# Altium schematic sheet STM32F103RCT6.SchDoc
size A3
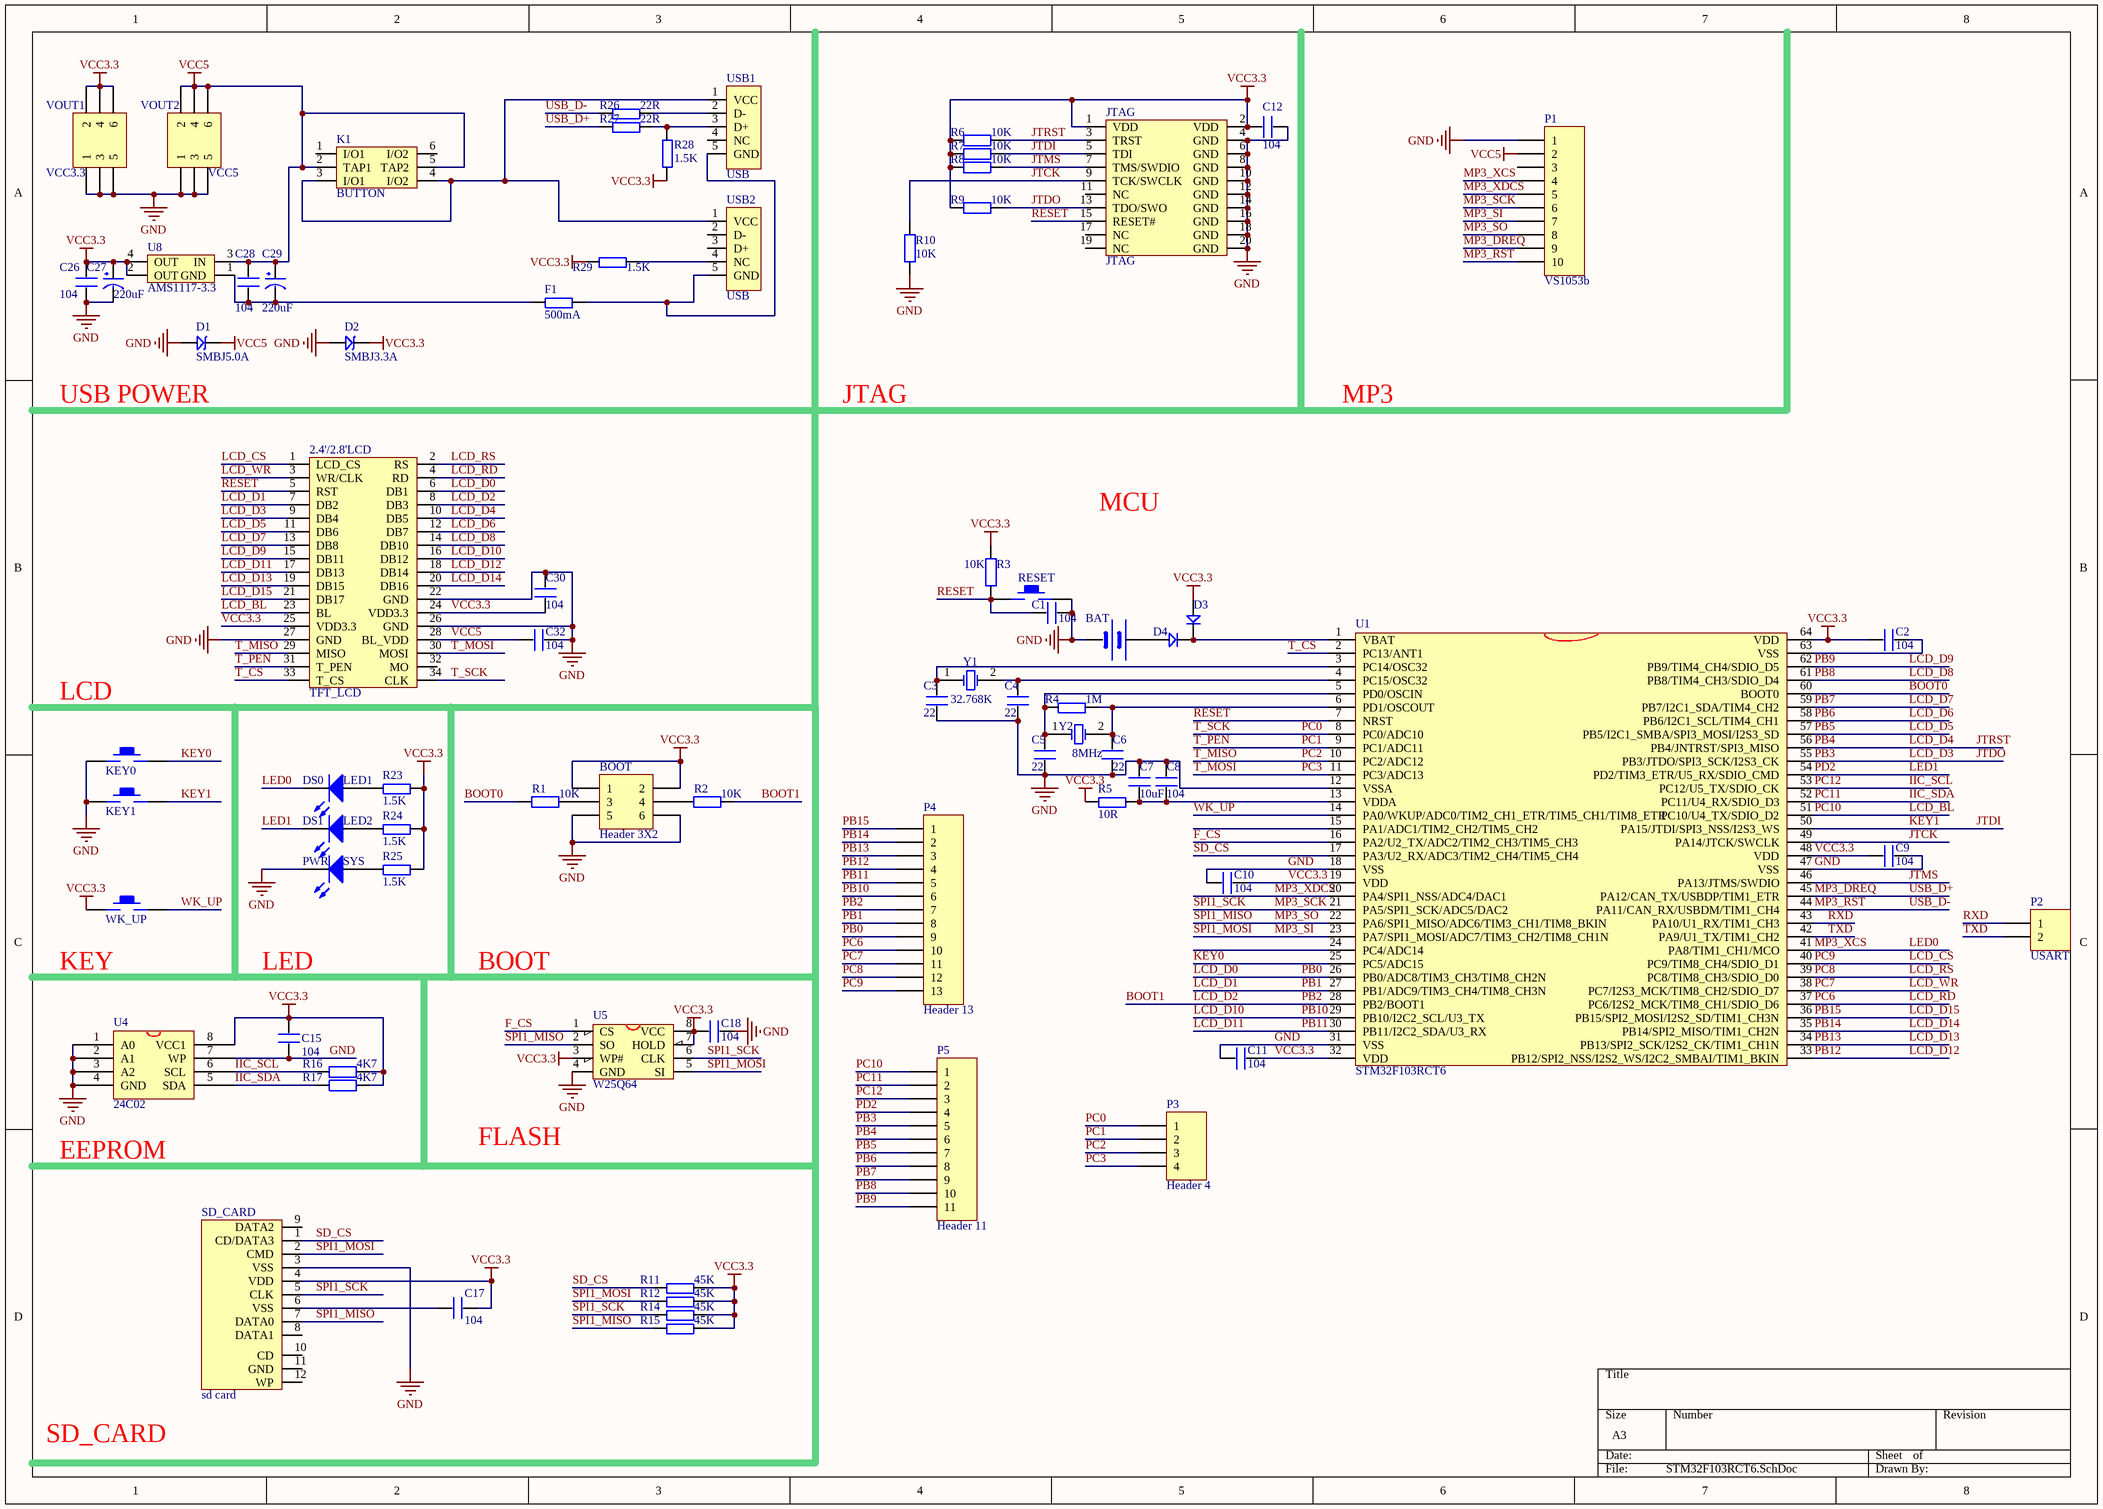
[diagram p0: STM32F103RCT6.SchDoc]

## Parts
2.4'/2.8'LCD  TFT_LCD  [HEAD2*17]
BAT  BATT  [BATM]  (value not drawn)
BOOT  Header 3X2  [HDR2X3]
C1  104  [0603P]
C2  104  [0603P]
C3  22  [0603P]
C4  22  [0603P]
C5  22  [0603P]
C6  22  [0603P]
C7  10uF  [0603P]
C8  104  [0603P]
C9  104  [0603P]
C10  104  [0603P]
C11  104  [0603P]
C12  104  [0603P]
C15  104  [0603P]
C17  104  [0603P]
C18  104  [0603P]
C26  104  [0603P]
C27  220uF  [CC6.56.5]
C28  104  [0603P]
C29  220uF  [CC6.56.5]
C30  104  [0603P]
C32  104  [0603P]
D1  SMBJ5.0A  [SMBJ]
D2  SMBJ3.3A  [SMBJ]
D3  1N4148  [DIODE_SOP]  (value not drawn)
D4  (no value)  [DIODE_SOP]
DS0  LED1  [SMDLED]
DS1  LED2  [SMDLED]
F1  500mA  [0805]
JTAG  JTAG  [JTAG_20]
K1  BUTTON  [BTN8.5*8.5]
KEY0  KEY_M  [KEY_M]  (value not drawn)
KEY1  KEY_M  [KEY_M]  (value not drawn)
P1  VS1053b  [HDR1X10]
P2  USART  [HDR1X2]
P3  Header 4  [HDR1X4]
P4  Header 13  [HDR1X13]
P5  Header 11  [HDR1X11]
PWR  SYS  [SMDLED]
R1  value 10K  [0603P]  (hidden comment: Res2)
R2  value 10K  [0603P]  (hidden comment: Res2)
R3  value 10K  [0603P]  (hidden comment: Res2)
R4  1M  [0603P]
R5  10R  [0603P]
R6  value 10K  [0603P]
R7  value 10K  [0603P]
R8  value 10K  [0603P]
R9  value 10K  [0603P]
R10  value 10K  [0603P]
R11  45K  [0603P]
R12  45K  [0603P]
R14  45K  [0603P]
R15  45K  [0603P]
R16  value 4K7  [0603P]
R17  value 4K7  [0603P]
R23  1.5K  [0603P]
R24  1.5K  [0603P]
R25  1.5K  [0603P]
R26  22R  [0603P]
R27  22R  [0603P]
R28  1.5K  [0603P]
R29  1.5K  [0603P]
RESET  KEY_M  [KEY_M]  (value not drawn)
SD_CARD  sd card  [SDCARD_L]
U1  STM32F103RCT6  [LQFP64]
U4  24C02  [SOP-8]
U5  W25Q64  [SOIC-8]
U8  AMS1117-3.3  [AMS1117]
USB1  USB  [USB/SM0.8-6H5]
USB2  USB  [USB/SM0.8-6H5]
VOUT1  VCC3.3  [HDR2X3]
VOUT2  VCC5  [HDR2X3]
WK_UP  KEY_M  [KEY_M]  (value not drawn)
Y1  32.768K  [XTAL32]
Y2  8MHz  [XTAL_US]

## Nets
GND: 2.4'/2.8'LCD.22(GND) 2.4'/2.8'LCD.26(GND) 2.4'/2.8'LCD.27(GND) BAT.2(GND) BOOT.5 BOOT.6 C1.2 C3.1 C4.1 C5.1 C6.1 C7.2 C8.2 C9.2 C10.1 C11.1 C12.2 C15.1 C18.2 C26.1 C27.2(GND) C30.2 C32.1 D1.1 D2.1 JTAG.4(GND) JTAG.6(GND) JTAG.8(GND) JTAG.10(GND) JTAG.12(GND) JTAG.14(GND) JTAG.16(GND) JTAG.18(GND) JTAG.20(GND) KEY0.1 KEY1.1 P1.1 PWR.2(K) R10.2 RESET.2 SD_CARD.3(VSS) U1.12(VSSA) U1.18(VSS) U1.31(VSS) U1.47(VSS) U4.1(A0) U4.2(A1) U4.3(A2) U4.4(GND) U4.7(WP) U5.4(GND) VOUT1.1 VOUT1.3 VOUT1.5 VOUT2.1 VOUT2.3 VOUT2.5
VCC3.3: 2.4'/2.8'LCD.24(VDD3.3) 2.4'/2.8'LCD.25(VDD3.3) BOOT.1 BOOT.2 C2.1 C9.1 C10.2 C11.2 C12.1 C15.2 C17.2 C18.1 C26.2 C27.1(VCC) C30.1 D2.2 D3.1 JTAG.1(VDD) JTAG.2(VDD) R3.2 R5.1 R6.1 R7.1 R8.1 R9.1 R11.2 R12.2 R14.2 R15.2 R16.2 R17.2 R23.2 R24.2 R25.2 R28.1 R29.1 SD_CARD.4(VDD) U1.19(VDD) U1.32(VDD) U1.48(VDD) U1.64(VDD) U4.8(VCC1) U5.3(WP#) U5.7(HOLD) U5.8(VCC) U8.2(OUT) U8.4(OUT) VOUT1.2 VOUT1.4 VOUT1.6 WK_UP.1
VCC5: 2.4'/2.8'LCD.28(BL_VDD) C28.2 C29.1(VCC) C32.2 D1.2 K1.2(TAP1) K1.5(TAP2) P1.2 U8.3(IN) VOUT2.2 VOUT2.4 VOUT2.6
BOOT0: R1.1 U1.60(BOOT0)
BOOT1: 2.4'/2.8'LCD.8(DB3) P4.7 R2.2 U1.28(PB2/BOOT1)  [also labelled LCD_D2, PB2]
F_CS: U1.16(PA2/U2_TX/ADC2/TIM2_CH3/TIM5_CH3) U5.1(CS)
IIC_SCL: P5.3 R16.1 U1.53(PC12/U5_TX/SDIO_CK) U4.6(SCL)  [also labelled PC12]
IIC_SDA: P5.2 R17.1 U1.52(PC11/U4_RX/SDIO_D3) U4.5(SDA)  [also labelled PC11]
JTCK: JTAG.9(TCK/SWCLK) R10.1 U1.49(PA14/JTCK/SWCLK)
JTDI: JTAG.5(TDI) KEY1.2 R7.2 U1.50(PA15/JTDI/SPI3_NSS/I2S3_WS)  [also labelled KEY1]
JTDO: 2.4'/2.8'LCD.9(DB4) JTAG.13(TDO/SWO) P5.5 R9.2 U1.55(PB3/JTDO/SPI3_SCK/I2S3_CK)  [also labelled LCD_D3, PB3]
JTMS: JTAG.7(TMS/SWDIO) R8.2 U1.46(PA13/JTMS/SWDIO)
JTRST: 2.4'/2.8'LCD.10(DB5) JTAG.3(TRST) P5.6 R6.2 U1.56(PB4/JNTRST/SPI3_MISO)  [also labelled LCD_D4, PB4]
KEY0: KEY0.2 U1.25(PC5/ADC15)
LCD_BL: 2.4'/2.8'LCD.23(BL) P5.1 U1.51(PC10/U4_TX/SDIO_D2)  [also labelled PC10]
LCD_CS: 2.4'/2.8'LCD.1(LCD_CS) P4.13 U1.40(PC9/TIM8_CH4/SDIO_D1)  [also labelled PC9]
LCD_D0: 2.4'/2.8'LCD.6(DB1) P4.9 U1.26(PB0/ADC8/TIM3_CH3/TIM8_CH2N)  [also labelled PB0]
LCD_D1: 2.4'/2.8'LCD.7(DB2) P4.8 U1.27(PB1/ADC9/TIM3_CH4/TIM8_CH3N)  [also labelled PB1]
LCD_D5: 2.4'/2.8'LCD.11(DB6) P5.7 U1.57(PB5/I2C1_SMBA/SPI3_MOSI/I2S3_SD)  [also labelled PB5]
LCD_D6: 2.4'/2.8'LCD.12(DB7) P5.8 U1.58(PB6/I2C1_SCL/TIM4_CH1)  [also labelled PB6]
LCD_D7: 2.4'/2.8'LCD.13(DB8) P5.9 U1.59(PB7/I2C1_SDA/TIM4_CH2)  [also labelled PB7]
LCD_D8: 2.4'/2.8'LCD.14(DB10) P5.10 U1.61(PB8/TIM4_CH3/SDIO_D4)  [also labelled PB8]
LCD_D9: 2.4'/2.8'LCD.15(DB11) P5.11 U1.62(PB9/TIM4_CH4/SDIO_D5)  [also labelled PB9]
LCD_D10: 2.4'/2.8'LCD.16(DB12) P4.6 U1.29(PB10/I2C2_SCL/U3_TX)  [also labelled PB10]
LCD_D11: 2.4'/2.8'LCD.17(DB13) P4.5 U1.30(PB11/I2C2_SDA/U3_RX)  [also labelled PB11]
LCD_D12: 2.4'/2.8'LCD.18(DB14) P4.4 U1.33(PB12/SPI2_NSS/I2S2_WS/I2C2_SMBAI/TIM1_BKIN)  [also labelled PB12]
LCD_D13: 2.4'/2.8'LCD.19(DB15) P4.3 U1.34(PB13/SPI2_SCK/I2S2_CK/TIM1_CH1N)  [also labelled PB13]
LCD_D14: 2.4'/2.8'LCD.20(DB16) P4.2 U1.35(PB14/SPI2_MISO/TIM1_CH2N)  [also labelled PB14]
LCD_D15: 2.4'/2.8'LCD.21(DB17) P4.1 U1.36(PB15/SPI2_MOSI/I2S2_SD/TIM1_CH3N)  [also labelled PB15]
LCD_RD: 2.4'/2.8'LCD.4(RD) P4.10 U1.37(PC6/I2S2_MCK/TIM8_CH1/SDIO_D6)  [also labelled PC6]
LCD_RS: 2.4'/2.8'LCD.2(RS) P4.12 U1.39(PC8/TIM8_CH3/SDIO_D0)  [also labelled PC8]
LCD_WR: 2.4'/2.8'LCD.3(WR/CLK) P4.11 U1.38(PC7/I2S3_MCK/TIM8_CH2/SDIO_D7)  [also labelled PC7]
LED0: DS0.2(K) P1.4 U1.41(PA8/TIM1_CH1/MCO)  [also labelled MP3_XCS]
LED1: DS1.2(K) P5.4 U1.54(PD2/TIM3_ETR/U5_RX/SDIO_CMD)  [also labelled PD2]
MP3_DREQ: P1.9 R27.1 U1.45(PA12/CAN_TX/USBDP/TIM1_ETR)  [also labelled USB_D+]
MP3_RST: P1.10 R26.1 U1.44(PA11/CAN_RX/USBDM/TIM1_CH4)  [also labelled USB_D-]
MP3_SCK: P1.6 R14.1 SD_CARD.5(CLK) U1.21(PA5/SPI1_SCK/ADC5/DAC2) U5.6(CLK)  [also labelled SPI1_SCK]
MP3_SI: P1.7 R12.1 SD_CARD.2(CMD) U1.23(PA7/SPI1_MOSI/ADC7/TIM3_CH2/TIM8_CH1N) U5.5(SI)  [also labelled SPI1_MOSI]
MP3_SO: P1.8 R15.1 SD_CARD.7(DATA0) U1.22(PA6/SPI1_MISO/ADC6/TIM3_CH1/TIM8_BKIN) U5.2(SO)  [also labelled SPI1_MISO]
MP3_XDCS: P1.5 U1.20(PA4/SPI1_NSS/ADC4/DAC1)
PC0: 2.4'/2.8'LCD.34(CLK) P3.1 U1.8(PC0/ADC10)  [also labelled T_SCK]
PC1: 2.4'/2.8'LCD.31(T_PEN) P3.2 U1.9(PC1/ADC11)  [also labelled T_PEN]
PC2: 2.4'/2.8'LCD.29(MISO) P3.3 U1.10(PC2/ADC12)  [also labelled T_MISO]
PC3: 2.4'/2.8'LCD.30(MOSI) P3.4 U1.11(PC3/ADC13)  [also labelled T_MOSI]
RESET: 2.4'/2.8'LCD.5(RST) C1.1 JTAG.15(RESET#) R3.1 RESET.1 U1.7(NRST)
RXD: P2.1 U1.43(PA10/U1_RX/TIM1_CH3)
SD_CS: R11.1 SD_CARD.1(CD/DATA3) U1.17(PA3/U2_RX/ADC3/TIM2_CH4/TIM5_CH4)
T_CS: 2.4'/2.8'LCD.33(T_CS) U1.2(PC13/ANT1)
TXD: P2.2 U1.42(PA9/U1_TX/TIM1_CH2)
WK_UP: U1.14(PA0/WKUP/ADC0/TIM2_CH1_ETR/TIM5_CH1/TIM8_ETR) WK_UP.2
NetBAT_1: BAT.1(VCC) D4.1
NetBOOT_3: BOOT.3 R1.2
NetBOOT_4: BOOT.4 R2.1
NetC2_2: C2.2 U1.63(VSS)
NetC3_2: C3.2 U1.3(PC14/OSC32) Y1.1(OSC1)
NetC4_2: C4.2 U1.4(PC15/OSC32) Y1.2(OSC2)
NetC5_2: C5.2 R4.1 U1.5(PD0/OSCIN) Y2.1(OSC1)
NetC6_2: C6.2 R4.2 U1.6(PD1/OSCOUT) Y2.2(OSC2)
NetC7_1: C7.1 C8.1 R5.2 U1.13(VDDA)
NetC17_1: C17.1 SD_CARD.6(VSS)
NetC28_1: C28.1 C29.2(GND) F1.1 U8.1(GND)
NetD3_2: D3.2 D4.2 U1.1(VBAT)
NetDS0_1: DS0.1(A) R23.1
NetDS1_1: DS1.1(A) R24.1
NetF1_2: F1.2 USB1.5(GND) USB2.5(GND)
NetK1_3: K1.3(I/O1) K1.4(I/O2) USB1.1(VCC) USB2.1(VCC)
NetPWR_1: PWR.1(A) R25.1
NetR26_2: R26.2 USB1.2(D-)
NetR27_2: R27.2 R28.2 USB1.3(D+)
NetR29_2: R29.2 USB2.4(NC)

Not connected (* = marked no-connect by the designer): 2.4'/2.8'LCD 32(MO); JTAG 11(NC) 17(NC) 19(NC); K1 1(I/O1) 6(I/O2); P1 3; SD_CARD 8(DATA1) 9(DATA2) 10(CD) 11(GND) 12(WP); U1 15(PA1/ADC1/TIM2_CH2/TIM5_CH2) 24(PC4/ADC14); USB1 4(NC); USB2 2(D-) 3(D+)

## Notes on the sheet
- (near D1) USB POWER
- JTAG
- MP3
- MCU
- LCD
- (near WK_UP) KEY
- LED
- BOOT
- (near U4) EEPROM
- FLASH
- SD_CARD

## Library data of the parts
BAT = BAT
BOOT VOUT1 VOUT2 = Header 3X2: Header, 3-Pin, Dual row
C1-C12 C15 C17 C18 C26 C28 C30 C32 = C
C27 C29 = CAP
D1 D2 = SMBJ: TVS
D3 = D
D4 = D: 1N4148
DS0 DS1 PWR = LED2: Typical RED, GREEN, YELLOW, AMBER GaAs LED
F1 R4 R5 R11 R12 R14 R15 R23-R29 = R
P1 = Header 10: Header, 10-Pin
P2 = Header 2: Header, 2-Pin
P3 = Header 4: Header, 4-Pin
P4 = Header 13: Header, 13-Pin
P5 = Header 11: Header, 11-Pin
R1-R3 R6-R10 R16 R17 = Res2: Resistor
U1 = STM32F103RDT6
U4 = 24C256
U5 = W25X16: W25X16;SST25VF016;MX25L1605
U8 = AMS1117
USB1 USB2 = USB5
Y1 Y2 = XTAL: Crystal Oscillator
